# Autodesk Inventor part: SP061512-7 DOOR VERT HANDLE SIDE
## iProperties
Created: 2012-06
Part Number: SP061512-7 DOOR VERT HANDLE SIDE
Material: Aluminum-6061
Description: CLAMP PROFILE 45X32
Document SubType Name: Modeling
Designer: Administrator
Stock Number: 20.1053 CLAMP PROFILE 45X32
Density: 2.71 g/cm^3
Mass: 3147.32 g
Surface Area: 7034.34 cm^2
Volume: 1161.37 cm^3
FINISH: CLEAR ANODIZED
Author: Administrator
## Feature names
1. Extrusion1
2. Hole1
